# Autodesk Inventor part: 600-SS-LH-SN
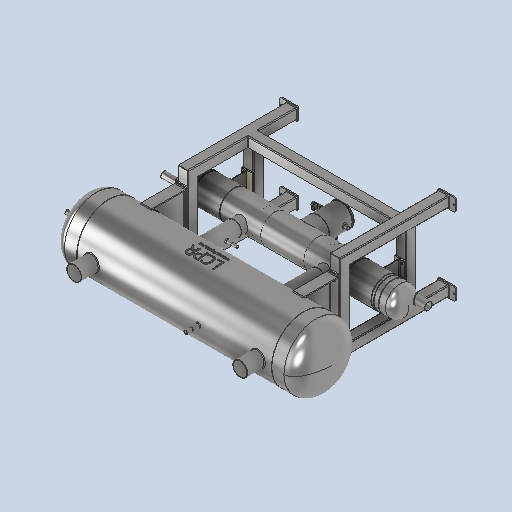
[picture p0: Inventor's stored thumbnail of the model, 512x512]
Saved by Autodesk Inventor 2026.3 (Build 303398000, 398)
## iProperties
Created: 2026-05
Part Number: 600-SS-LH-SN
Material: Generic
Document SubType Name: Modeling
Designer: rva
Density: 1 g/cm^3
Appearance: Default
Author: rva
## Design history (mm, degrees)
derived "LCPR-SS-600-FULL-ASSEMBLY-LH-SN.iam"
body "Solid1"
node "LCPR-SS-600-FULL FRAME ASSEMBLY.iam:1::LCPR-SS-600-FRAME ASS"
node "LCPR-SS-600-1840-125-SN-WELD.iam:1::600 mm Dome End Cap.ipt:"
node "LCPR-SS-600-1840-125-SN-WELD.iam:1::600 mm Dome End Cap.ipt:"
node "LCPR-SS-600-1840-125-SN-WELD.iam:1::LPR-600-Leg Assembly.iam"
node "LCPR-SS-600-1840-125-SN-WELD.iam:1::LPR-600-Leg Assembly.iam"
node "LCPR-SS-600-1840-125-SN-WELD.iam:1::H1100-R.ipt:1"
node "LCPR-SS-600-1840-125-SN-WELD.iam:1::LCPR-LOGO.ipt:1"
node "LCPR-SS-600-1840-125-SN-WELD.iam:1::Welds"
node "Sub-SS-250-125-1712-52-10-65-50-LH.iam:1::SS-250-52 hole Sub"
node "Sub-SS-250-125-1712-52-10-65-50-LH.iam:1::SS-250-52 hole Sub"
node "Sub-SS-250-125-1712-52-10-65-50-LH.iam:1::SS-250 mm Subcoole"
node "Sub-SS-250-125-1712-52-10-65-50-LH.iam:1::SS-250 mm Subcoole"
node "Sub-SS-250-125-1712-52-10-65-50-LH.iam:1::H1100-R.ipt:2"
node "Sub-SS-250-125-1712-52-10-65-50-LH.iam:1::Welds"
node "Sub-SS-250-125-1712-52-10-65-50-LH.iam:1::1-2 Inch NPT Socke"
node "Sub-SS-250-125-1712-52-10-65-50-LH.iam:1::200 mm Oil Pot Ass"
node "AS 1111 - Metric M10 x 130:2"
node "AS 1111 - Metric M10 x 130:1"
node "AS 1111 - Metric M10 x 130:4"
node "AS 1111 - Metric M10 x 130:3"
node "AS 1111 - Metric M12 x 140:2"
node "AS 1111 - Metric M12 x 140:1"
node "AS 1111 - Metric M10 x 140:1"
node "AS 1111 - Metric M10 x 140:2"
node "AS 1112 (4) - Metric M12:1"
node "AS 1112 (4) - Metric M12:4"
node "AS 1112 (4) - Metric M12:3"
node "AS 1112 (4) - Metric M10:4"
node "AS 1112 (4) - Metric M10:3"
node "AS 1112 (4) - Metric M10:1"
node "AS 1112 (4) - Metric M10:2"
node "AS 1237 (4.1) 10 mm:9"
node "AS 1237 (4.1) 10 mm:6"
node "AS 1237 (4.1) 10 mm:7"
node "AS 1237 (4.1) 10 mm:8"
node "AS 1237 (4.1) 10 mm:10"
node "AS 1237 (4.1) 10 mm:4"
node "AS 1237 (4.1) 10 mm:5"
node "AS 1237 (4.1) 10 mm:11"
node "AS 1237 (4.1) 12 mm:1"
node "AS 1237 (4.1) 10 mm:2"
node "AS 1237 (4.1) 10 mm:3"
node "AS 1237 (4.1) 12 mm:2"
node "AS 1237 (4.1) 12 mm:5"
node "AS 1237 (4.1) 12 mm:4"
node "AS 1237 (4.1) 12 mm:6"
node "AS 1237 (4.1) 12 mm:3"
node "Nylon Heat Tranfer Spacer 568x100.ipt:1"
node "Nylon Heat Tranfer Spacer 568x100.ipt:2"
node "Nylon Heat Tranfer Spacer 175x100.ipt:1"
node "Nylon Heat Tranfer Spacer 175x100.ipt:2"
node "AS 1112 (4) - Metric M12:2"
node "Welds"
node "LCPR-SS-600-FULL-ASSEMBLY-LH-SN.iam_Bodies"
